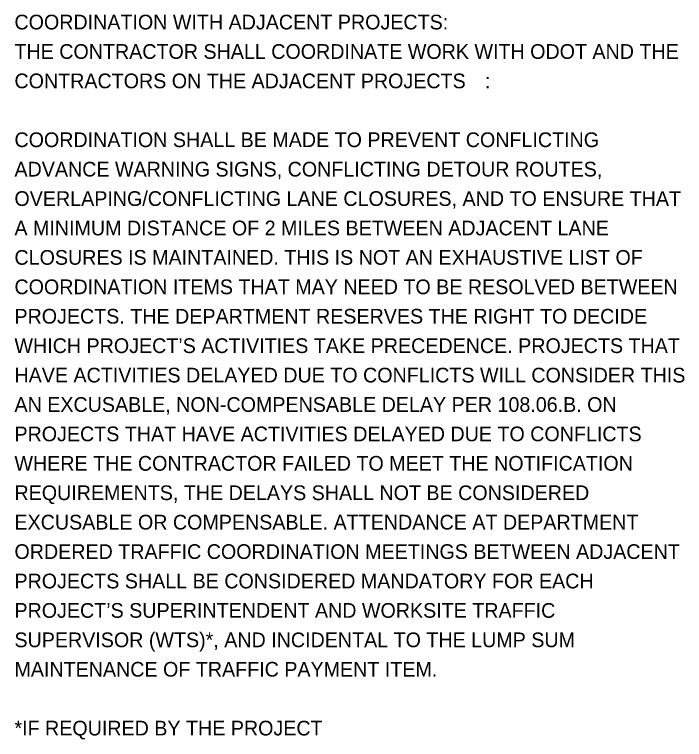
# Model space of a CAD drawing. Extents: x 63 to 145.9, y -75 to 21.1.
# Drawn here: x 134.43 to 140.8, y -15.37 to -8.46 of the extents above; entities that cross this region are included whole.
import ezdxf

# ---------------------------------------------------------------- set-up
doc = ezdxf.new("R2010")
doc.units = 0
doc.layers.add('AP_P_Airside', color=7, linetype='Continuous')

msp = doc.modelspace()

# ---------------------------------------------------------------- texts
at = {"layer": 'AP_P_Airside'}
for s, p in [('COORDINATION WITH ADJACENT PROJECTS:', (134.4264, -8.6069)), ('THE CONTRACTOR SHALL COORDINATE WORK WITH ODOT AND THE ', (134.4264, -8.8869)), ('CONTRACTORS ON THE ADJACENT PROJECTS', (134.4264, -9.1669)), (': ', (138.9047, -9.1669)), ('COORDINATION SHALL BE MADE TO PREVENT CONFLICTING ', (134.4264, -9.7269)), ('ADVANCE WARNING SIGNS, CONFLICTING DETOUR ROUTES, ', (134.4264, -10.0069)), ('OVERLAPING/CONFLICTING LANE CLOSURES, AND TO ENSURE THAT ', (134.4264, -10.2869)), ('A MINIMUM DISTANCE OF 2 MILES BETWEEN ADJACENT LANE ', (134.4264, -10.5669)), ('CLOSURES IS MAINTAINED. THIS IS NOT AN EXHAUSTIVE LIST OF ', (134.4264, -10.8469)), ('COORDINATION ITEMS THAT MAY NEED TO BE RESOLVED BETWEEN ', (134.4264, -11.1269)), ('PROJECTS. THE DEPARTMENT RESERVES THE RIGHT TO DECIDE ', (134.4264, -11.4069)), ('WHICH PROJECT’S ACTIVITIES TAKE PRECEDENCE. PROJECTS THAT ', (134.4264, -11.6869)), ('HAVE ACTIVITIES DELAYED DUE TO CONFLICTS WILL CONSIDER THIS ', (134.4264, -11.9669)), ('AN EXCUSABLE, NON-COMPENSABLE DELAY PER 108.06.B. ON ', (134.4264, -12.2469)), ('PROJECTS THAT HAVE ACTIVITIES DELAYED DUE TO CONFLICTS ', (134.4264, -12.5269)), ('WHERE THE CONTRACTOR FAILED TO MEET THE NOTIFICATION ', (134.4264, -12.8069)), ('REQUIREMENTS, THE DELAYS SHALL NOT BE CONSIDERED ', (134.4264, -13.0869)), ('EXCUSABLE OR COMPENSABLE. ATTENDANCE AT DEPARTMENT ', (134.4264, -13.3669)), ('ORDERED TRAFFIC COORDINATION MEETINGS BETWEEN ADJACENT ', (134.4264, -13.6469)), ('PROJECTS SHALL BE CONSIDERED MANDATORY FOR EACH ', (134.4264, -13.9269)), ('PROJECT’S SUPERINTENDENT AND WORKSITE TRAFFIC ', (134.4264, -14.2069)), ('SUPERVISOR (WTS)*, AND INCIDENTAL TO THE LUMP SUM ', (134.4264, -14.4869)), ('MAINTENANCE OF TRAFFIC PAYMENT ITEM.', (134.4264, -14.7669)), ('*IF REQUIRED BY THE PROJECT', (134.4264, -15.3269))]:
    msp.add_text(s, height=0.14, dxfattribs=at).set_placement(p)

doc.saveas('drawing.dxf')
